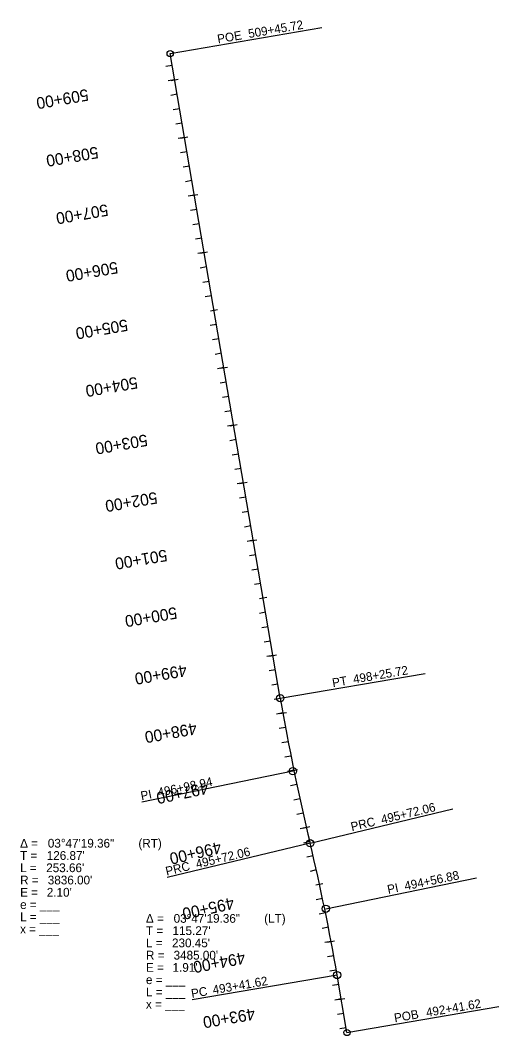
# Model space of a CAD drawing. Extents: x 11526299 to 11527120, y 9592436 to 9594175.
import ezdxf

# ---------------------------------------------------------------- set-up
doc = ezdxf.new("R2010")
doc.units = 0
for name, color, linetype in [('Alignment', 7, 'Continuous'), ('TextAlignment', 7, 'Continuous'), ('TextAlignmentLrg', 7, 'Continuous'), ('TextAlignmentSml', 7, 'Continuous')]:
    doc.layers.add(name, color=color, linetype=linetype)

msp = doc.modelspace()

# ---------------------------------------------------------------- linework, layer by layer
at = {"layer": 'Alignment'}
for p, q in [((11526745.2, 9593013.8), (11526556.3, 9594117.8)), ((11526745.2, 9593013.8), (11526556.3, 9594117.8)), ((11526859.5, 9592441.2), (11526842.6, 9592539.7)), ((11526859.5, 9592441.2), (11526842.6, 9592539.7))]:
    msp.add_line(p, q, dxfattribs=at)
for centre, radius, start, end in [((11530526.2, 9593661), 3836, 189.7133, 193.502), ((11530526.2, 9593661), 3836, 189.7133, 193.502), ((11523407.6, 9591951.7), 3485, 9.7133, 13.502), ((11523407.6, 9591951.7), 3485, 9.7133, 13.502)]:
    msp.add_arc(centre, radius, start, end, dxfattribs=at)
at = {"layer": 'TextAlignment'}
for p, q in [((11526556.3, 9594117.8), (11526816.5, 9594162.3)), ((11526816.5, 9594162.3), (11526816.5, 9594162.3)), ((11526745.2, 9593013.8), (11526993.6, 9593056.3)), ((11526993.6, 9593056.3), (11526993.6, 9593056.3)), ((11526766.6, 9592888.8), (11526508, 9592835.7)), ((11526508, 9592835.7), (11526508, 9592835.7)), ((11526796.3, 9592765.4), (11527041.3, 9592824.2)), ((11527041.3, 9592824.2), (11527041.3, 9592824.2)), ((11526796.3, 9592765.4), (11526551.2, 9592706.6)), ((11526551.2, 9592706.6), (11526551.2, 9592706.6)), ((11526823.2, 9592653.3), (11527081.8, 9592706.4)), ((11527081.8, 9592706.4), (11527081.8, 9592706.4)), ((11526842.6, 9592539.7), (11526594.2, 9592497.2)), ((11526594.2, 9592497.2), (11526594.2, 9592497.2)), ((11526859.5, 9592441.2), (11527119.7, 9592485.7)), ((11527119.7, 9592485.7), (11527119.7, 9592485.7))]:
    msp.add_line(p, q, dxfattribs=at)
for centre, radius in [((11526556.3, 9594117.8), 5.34), ((11526745.2, 9593013.8), 6.24), ((11526766.6, 9592888.8), 6.24), ((11526796.3, 9592765.4), 6.24), ((11526796.3, 9592765.4), 6.24), ((11526823.2, 9592653.3), 6.24), ((11526842.6, 9592539.7), 6.24), ((11526859.5, 9592441.2), 5.34)]:
    msp.add_circle(centre, radius, dxfattribs=at)
at = {"layer": 'TextAlignmentLrg'}
for p, q in [((11526564, 9594072.7), (11526553.2, 9594070.9)), ((11526580.8, 9593974.1), (11526570.1, 9593972.3)), ((11526597.7, 9593875.6), (11526587, 9593873.7)), ((11526614.6, 9593777), (11526603.8, 9593775.2)), ((11526625.4, 9593677.4), (11526637.5, 9593679.5)), ((11526648.3, 9593579.9), (11526637.6, 9593578)), ((11526665.2, 9593481.3), (11526654.4, 9593479.5)), ((11526682.1, 9593382.7), (11526671.3, 9593380.9)), ((11526698.9, 9593284.2), (11526688.2, 9593282.3)), ((11526709.8, 9593184.6), (11526721.9, 9593186.6)), ((11526732.7, 9593087), (11526721.9, 9593085.2)), ((11526749.6, 9592988.5), (11526738.9, 9592986.6)), ((11526768.5, 9592890.3), (11526757.8, 9592888.1)), ((11526789.8, 9592792.6), (11526779.2, 9592790.1)), ((11526806.4, 9592693.9), (11526818.3, 9592696.5)), ((11526832.3, 9592597.2), (11526821.5, 9592595.2)), ((11526849.6, 9592498.7), (11526838.9, 9592496.9))]:
    msp.add_line(p, q, dxfattribs=at)
at = {"layer": 'TextAlignmentSml'}
for p, q in [((11526559.8, 9594097.4), (11526549, 9594095.5)), ((11526557.9, 9594071.7), (11526570, 9594073.7)), ((11526568.2, 9594048.1), (11526557.4, 9594046.2)), ((11526572.4, 9594023.4), (11526561.6, 9594021.6)), ((11526576.6, 9593998.8), (11526565.9, 9593996.9)), ((11526574.8, 9593973.1), (11526586.9, 9593975.2)), ((11526585.1, 9593949.5), (11526574.3, 9593947.7)), ((11526589.3, 9593924.9), (11526578.5, 9593923)), ((11526593.5, 9593900.2), (11526582.7, 9593898.4)), ((11526591.7, 9593874.5), (11526603.7, 9593876.6)), ((11526601.9, 9593850.9), (11526591.2, 9593849.1)), ((11526606.2, 9593826.3), (11526595.4, 9593824.5)), ((11526610.4, 9593801.7), (11526599.6, 9593799.8)), ((11526608.6, 9593776), (11526620.6, 9593778)), ((11526618.8, 9593752.4), (11526608, 9593750.5)), ((11526623, 9593727.7), (11526612.3, 9593725.9)), ((11526627.2, 9593703.1), (11526616.5, 9593701.2)), ((11526625.4, 9593677.4), (11526637.5, 9593679.5)), ((11526635.7, 9593653.8), (11526624.9, 9593652)), ((11526639.9, 9593629.2), (11526629.1, 9593627.3)), ((11526644.1, 9593604.5), (11526633.4, 9593602.7)), ((11526642.3, 9593578.8), (11526654.4, 9593580.9)), ((11526652.5, 9593555.2), (11526641.8, 9593553.4)), ((11526656.8, 9593530.6), (11526646, 9593528.8)), ((11526661, 9593506), (11526650.2, 9593504.1)), ((11526659.2, 9593480.3), (11526671.2, 9593482.3)), ((11526669.4, 9593456.7), (11526658.7, 9593454.8)), ((11526673.6, 9593432), (11526662.9, 9593430.2)), ((11526677.9, 9593407.4), (11526667.1, 9593405.5)), ((11526676, 9593381.7), (11526688.1, 9593383.8)), ((11526686.3, 9593358.1), (11526675.5, 9593356.3)), ((11526690.5, 9593333.5), (11526679.7, 9593331.6)), ((11526694.7, 9593308.8), (11526684, 9593307)), ((11526692.9, 9593283.1), (11526705, 9593285.2)), ((11526703.2, 9593259.5), (11526692.4, 9593257.7)), ((11526707.4, 9593234.9), (11526696.6, 9593233.1)), ((11526711.6, 9593210.3), (11526700.8, 9593208.4)), ((11526709.8, 9593184.6), (11526721.9, 9593186.6)), ((11526720, 9593161), (11526709.3, 9593159.1)), ((11526724.3, 9593136.3), (11526713.5, 9593134.5)), ((11526728.5, 9593111.7), (11526717.7, 9593109.8)), ((11526726.7, 9593086), (11526738.7, 9593088.1)), ((11526736.9, 9593062.4), (11526726.1, 9593060.6)), ((11526741.1, 9593037.8), (11526730.4, 9593035.9)), ((11526745.3, 9593013.1), (11526734.6, 9593011.3)), ((11526743.6, 9592987.4), (11526755.7, 9592989.6)), ((11526754.1, 9592963.9), (11526743.4, 9592961.9)), ((11526758.7, 9592939.3), (11526748, 9592937.3)), ((11526763.5, 9592914.8), (11526752.8, 9592912.7)), ((11526762.5, 9592889.1), (11526774.5, 9592891.5)), ((11526773.6, 9592865.8), (11526762.9, 9592863.5)), ((11526778.8, 9592841.4), (11526768.2, 9592839)), ((11526784.2, 9592817), (11526773.6, 9592814.6)), ((11526783.9, 9592791.2), (11526795.8, 9592794)), ((11526795.6, 9592768.3), (11526784.9, 9592765.7)), ((11526801.3, 9592743.9), (11526790.7, 9592741.5)), ((11526806.9, 9592719.6), (11526796.3, 9592717.2)), ((11526806.4, 9592693.9), (11526818.3, 9592696.5)), ((11526817.6, 9592670.7), (11526806.9, 9592668.5)), ((11526822.7, 9592646.2), (11526812, 9592644.1)), ((11526827.6, 9592621.7), (11526816.8, 9592619.6)), ((11526826.3, 9592596), (11526838.3, 9592598.3)), ((11526836.8, 9592572.6), (11526826.1, 9592570.6)), ((11526841.2, 9592548), (11526830.4, 9592546.1)), ((11526845.4, 9592523.3), (11526834.7, 9592521.5)), ((11526843.6, 9592497.7), (11526855.7, 9592499.7)), ((11526853.9, 9592474.1), (11526843.1, 9592472.2)), ((11526858.1, 9592449.4), (11526847.3, 9592447.6))]:
    msp.add_line(p, q, dxfattribs=at)

# ---------------------------------------------------------------- texts
at = {"layer": 'TextAlignment'}
for s, rotation, p in [('509+45.72', 9.7133, (11526691.5, 9594144.3)), ('POE ', 9.7133, (11526638.5, 9594135.2)), ('498+25.72', 9.7133, (11526871.3, 9593038.8)), ('PT', 9.7133, (11526835.5, 9593032.6)), ('496+98.94', 11.6076, (11526536.6, 9592844.9)), ('PI ', 11.6076, (11526507.4, 9592838.9)), ('495+72.06', 13.502, (11526919.8, 9592798.4)), ('PRC', 13.502, (11526868, 9592786)), ('495+72.06', 13.502, (11526602.2, 9592722.2)), ('PRC', 13.502, (11526550.4, 9592709.8)), ('494+56.88', 11.6076, (11526959.6, 9592684.7)), ('PI ', 11.6076, (11526930.3, 9592678.7)), ('493+41.62', 9.7133, (11526630.5, 9592506.7)), ('PC', 9.7133, (11526593.7, 9592500.4)), ('492+41.62', 9.7133, (11526996.4, 9592467.9)), ('POB ', 9.7133, (11526941.7, 9592458.6))]:
    msp.add_text(s, height=15, rotation=rotation, dxfattribs=at).set_placement(p)
for s, p in [('Δ = ', (11526299.1, 9592757.9)), ('03°47\'19.36"', (11526346.6, 9592757.9)), (' (RT)', (11526496.3, 9592757.9)), ('T = ', (11526299.1, 9592736.9)), ("126.87'", (11526344.7, 9592736.9)), ('L = ', (11526299.1, 9592715.9)), ("253.66'", (11526343.8, 9592715.9)), ('R = ', (11526299.1, 9592694.9)), ("3836.00'", (11526346.5, 9592694.9)), ('E = ', (11526299.1, 9592673.9)), ("2.10'", (11526344.8, 9592673.9)), ('e = ___ ', (11526299.1, 9592652.9)), ('L = ___', (11526299.1, 9592631.9)), (' (LT)', (11526712, 9592629.2)), ('Δ = ', (11526514.8, 9592629.2)), ('03°47\'19.36"', (11526562.3, 9592629.2)), ('x = ___', (11526299.1, 9592610.9)), ('T = ', (11526514.8, 9592608.2)), ("115.27'", (11526560.4, 9592608.2)), ('L = ', (11526514.8, 9592587.2)), ("230.45'", (11526559.5, 9592587.2)), ('R = ', (11526514.8, 9592566.2)), ("3485.00'", (11526562.2, 9592566.2)), ('E = ', (11526514.8, 9592545.2)), ("1.91'", (11526560.4, 9592545.2)), ('e = ___ ', (11526514.8, 9592524.2)), ('L = ___', (11526514.8, 9592503.2)), ('x = ___', (11526514.8, 9592482.2))]:
    msp.add_text(s, height=15, dxfattribs=at).set_placement(p)
at = {"layer": 'TextAlignmentLrg'}
for s, rotation, p in [('505+00', 189.7133, (11526481.9, 9593663)), ('500+00', 189.7133, (11526566.3, 9593170.2)), ('495+00', 192.3172, (11526663.7, 9592673))]:
    msp.add_text(s, height=20.04, rotation=rotation, dxfattribs=at).set_placement(p)
at = {"layer": 'TextAlignmentSml'}
for s, rotation, p in [('509+00', 189.7133, (11526414.4, 9594057.3)), ('508+00', 189.7133, (11526431.3, 9593958.7)), ('507+00', 189.7133, (11526448.2, 9593860.1)), ('506+00', 189.7133, (11526465, 9593761.6)), ('505+00', 189.7133, (11526481.9, 9593663)), ('504+00', 189.7133, (11526498.8, 9593564.4)), ('503+00', 189.7133, (11526515.7, 9593465.9)), ('502+00', 189.7133, (11526532.5, 9593367.3)), ('501+00', 189.7133, (11526549.4, 9593268.7)), ('500+00', 189.7133, (11526566.3, 9593170.2)), ('499+00', 189.7133, (11526583.2, 9593071.6)), ('498+00', 190.0974, (11526600.2, 9592972.1)), ('497+00', 191.5911, (11526619.5, 9592870)), ('496+00', 193.0847, (11526641.5, 9592768.4)), ('495+00', 192.3172, (11526663.7, 9592673)), ('494+00', 190.6732, (11526683, 9592579.2)), ('493+00', 189.7133, (11526700.1, 9592483.3))]:
    msp.add_text(s, height=20.04, rotation=rotation, dxfattribs=at).set_placement(p)

doc.saveas('drawing.dxf')
